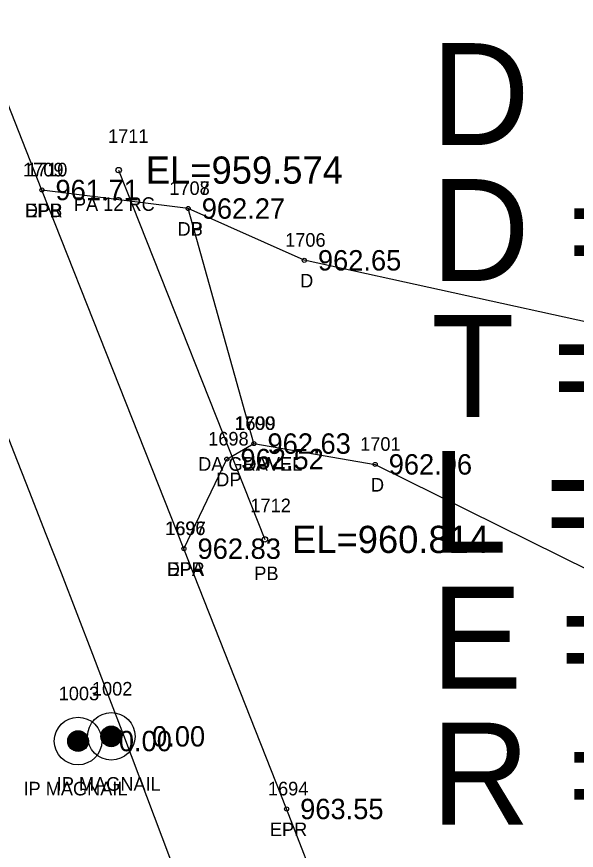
# Model space of a CAD drawing. Extents: x 1528109 to 1531398, y 1157799 to 1162548.
# Drawn here: x 1530615.5 to 1530656.7, y 1158820.1 to 1158881.4 of the extents above; entities that cross this region are included whole.
import ezdxf

# ---------------------------------------------------------------- set-up
doc = ezdxf.new("R2010")
doc.units = 0
for name, color, linetype in [('RD_EX_DR_Pipe', 7, 'Continuous'), ('RD_EX_DR_Pipe_txCode', 7, 'Continuous'), ('RD_EX_Driveway', 7, 'Continuous'), ('RD_EX_Driveway_txCode', 7, 'Continuous'), ('RD_EX_DV_Prop_txCode', 7, 'Continuous'), ('RD_EX_DV_PropPin', 7, 'Continuous'), ('RD_EX_Road', 7, 'Continuous'), ('RD_EX_Road_txCode', 7, 'Continuous'), ('RD_EX_TX_Driveway_ELEV', 7, 'Continuous'), ('RD_EX_TX_DV_Prop_ELEV', 7, 'Continuous'), ('RD_EX_TX_Road_ELEV', 7, 'Continuous'), ('RD_HC_Cl', 7, 'Continuous'), ('RD_HC_Data', 7, 'Continuous'), ('RD_SMD_Locator', 7, 'Continuous'), ('RD_TX_Pipe_ElevEX', 7, 'Continuous')]:
    doc.layers.add(name, color=color, linetype=linetype)

msp = doc.modelspace()

# ---------------------------------------------------------------- linework, layer by layer
at = {"layer": 'RD_EX_DR_Pipe'}
msp.add_line((1530622.995, 1158870.158), (1530633.756, 1158842.986), dxfattribs=at)
at = {"layer": 'RD_EX_Driveway'}
for points in [[(1530627.8, 1158842.302), (1530630.956, 1158848.893), (1530632.946, 1158850.037), (1530628.109, 1158867.33), (1530617.346, 1158868.693)], [(1530632.946, 1158850.037), (1530641.869, 1158848.504), (1530662.26, 1158838.421), (1530704.169, 1158845.738), (1530700.829, 1158858.174), (1530669.534, 1158856.332), (1530636.658, 1158863.52), (1530628.109, 1158867.33)]]:
    msp.add_lwpolyline(points, dxfattribs=at)
at = {"layer": 'RD_EX_DV_PropPin'}
for p, q in [((1530619.727, 1158827.441), (1530619.727, 1158828.856)), ((1530619.762, 1158827.428), (1530619.762, 1158828.869)), ((1530619.797, 1158827.417), (1530619.797, 1158828.88)), ((1530619.833, 1158827.408), (1530619.833, 1158828.89)), ((1530619.868, 1158827.401), (1530619.868, 1158828.897)), ((1530619.903, 1158827.395), (1530619.903, 1158828.903)), ((1530619.938, 1158827.391), (1530619.938, 1158828.907)), ((1530619.973, 1158827.389), (1530619.973, 1158828.909)), ((1530620.008, 1158827.388), (1530620.008, 1158828.91)), ((1530620.043, 1158827.389), (1530620.043, 1158828.909)), ((1530620.078, 1158827.391), (1530620.078, 1158828.907)), ((1530620.113, 1158827.395), (1530620.113, 1158828.903)), ((1530620.148, 1158827.401), (1530620.148, 1158828.897)), ((1530620.183, 1158827.408), (1530620.183, 1158828.89)), ((1530620.218, 1158827.417), (1530620.218, 1158828.88)), ((1530620.253, 1158827.428), (1530620.253, 1158828.869)), ((1530620.288, 1158827.441), (1530620.288, 1158828.856)), ((1530621.789, 1158828.126), (1530621.789, 1158828.865)), ((1530621.824, 1158828.069), (1530621.824, 1158828.922)), ((1530621.859, 1158828.021), (1530621.859, 1158828.969)), ((1530621.894, 1158827.98), (1530621.894, 1158829.01)), ((1530621.929, 1158827.944), (1530621.929, 1158829.046)), ((1530621.964, 1158827.913), (1530621.964, 1158829.077)), ((1530621.999, 1158827.885), (1530621.999, 1158829.105)), ((1530622.034, 1158827.861), (1530622.034, 1158829.13)), ((1530622.069, 1158827.839), (1530622.069, 1158829.151)), ((1530622.104, 1158827.819), (1530622.104, 1158829.171)), ((1530622.139, 1158827.802), (1530622.139, 1158829.188)), ((1530622.174, 1158827.788), (1530622.174, 1158829.203)), ((1530622.209, 1158827.775), (1530622.209, 1158829.216)), ((1530622.244, 1158827.764), (1530622.244, 1158829.227)), ((1530622.279, 1158827.754), (1530622.279, 1158829.236)), ((1530622.314, 1158827.747), (1530622.314, 1158829.243)), ((1530622.349, 1158827.741), (1530622.349, 1158829.249)), ((1530622.384, 1158827.737), (1530622.384, 1158829.253)), ((1530622.419, 1158827.735), (1530622.419, 1158829.255)), ((1530622.454, 1158827.734), (1530622.454, 1158829.256)), ((1530622.489, 1158827.735), (1530622.489, 1158829.255)), ((1530622.525, 1158827.737), (1530622.525, 1158829.253)), ((1530622.56, 1158827.741), (1530622.56, 1158829.249)), ((1530622.595, 1158827.747), (1530622.595, 1158829.243)), ((1530622.63, 1158827.754), (1530622.63, 1158829.236)), ((1530622.665, 1158827.764), (1530622.665, 1158829.227)), ((1530622.7, 1158827.775), (1530622.7, 1158829.216)), ((1530622.735, 1158827.788), (1530622.735, 1158829.203)), ((1530622.77, 1158827.802), (1530622.77, 1158829.188)), ((1530622.805, 1158827.819), (1530622.805, 1158829.171)), ((1530622.84, 1158827.839), (1530622.84, 1158829.151)), ((1530622.875, 1158827.861), (1530622.875, 1158829.13)), ((1530622.91, 1158827.885), (1530622.91, 1158829.105)), ((1530622.945, 1158827.913), (1530622.945, 1158829.077)), ((1530622.98, 1158827.944), (1530622.98, 1158829.046)), ((1530623.015, 1158827.98), (1530623.015, 1158829.01)), ((1530623.05, 1158828.021), (1530623.05, 1158828.969)), ((1530623.085, 1158828.069), (1530623.085, 1158828.922)), ((1530623.12, 1158828.126), (1530623.12, 1158828.865)), ((1530619.272, 1158827.953), (1530619.272, 1158828.345)), ((1530619.307, 1158827.851), (1530619.307, 1158828.447)), ((1530619.342, 1158827.779), (1530619.342, 1158828.518)), ((1530619.377, 1158827.722), (1530619.377, 1158828.575)), ((1530619.412, 1158827.675), (1530619.412, 1158828.623)), ((1530619.447, 1158827.634), (1530619.447, 1158828.664)), ((1530619.482, 1158827.598), (1530619.482, 1158828.7)), ((1530619.517, 1158827.567), (1530619.517, 1158828.731)), ((1530619.552, 1158827.539), (1530619.552, 1158828.759)), ((1530619.587, 1158827.514), (1530619.587, 1158828.783)), ((1530619.622, 1158827.493), (1530619.622, 1158828.805)), ((1530619.657, 1158827.473), (1530619.657, 1158828.825)), ((1530619.692, 1158827.456), (1530619.692, 1158828.842)), ((1530620.323, 1158827.456), (1530620.323, 1158828.842)), ((1530620.358, 1158827.473), (1530620.358, 1158828.825)), ((1530620.393, 1158827.493), (1530620.393, 1158828.805)), ((1530620.428, 1158827.514), (1530620.428, 1158828.783)), ((1530620.463, 1158827.539), (1530620.463, 1158828.759)), ((1530620.498, 1158827.567), (1530620.498, 1158828.731)), ((1530620.533, 1158827.598), (1530620.533, 1158828.7)), ((1530620.568, 1158827.634), (1530620.568, 1158828.664)), ((1530620.603, 1158827.675), (1530620.603, 1158828.623)), ((1530620.638, 1158827.722), (1530620.638, 1158828.575)), ((1530620.673, 1158827.779), (1530620.673, 1158828.518)), ((1530620.708, 1158827.851), (1530620.708, 1158828.447)), ((1530620.743, 1158827.953), (1530620.743, 1158828.345)), ((1530621.719, 1158828.299), (1530621.719, 1158828.691)), ((1530621.754, 1158828.197), (1530621.754, 1158828.793)), ((1530623.155, 1158828.197), (1530623.155, 1158828.793)), ((1530623.19, 1158828.299), (1530623.19, 1158828.691))]:
    msp.add_line(p, q, dxfattribs=at)
for centre, radius in [((1530622.454, 1158828.495), 1.75), ((1530620.008, 1158828.149), 1.75), ((1530620.008, 1158828.149), 0.761), ((1530622.454, 1158828.495), 0.761)]:
    msp.add_circle(centre, radius, dxfattribs=at)
at = {"layer": 'RD_EX_Road'}
msp.add_lwpolyline([(1530704.872, 1158597.47), (1530691.014, 1158649.877), (1530681.221, 1158687.321), (1530670.59, 1158724.996), (1530654.416, 1158774.072), (1530635.351, 1158823.151), (1530627.8, 1158842.302), (1530617.346, 1158868.693), (1530597.914, 1158918.043), (1530578.532, 1158967.566), (1530556.701, 1159015.656), (1530524.512, 1159062.454), (1530499.94, 1159086.31), (1530481.928, 1159100.117), (1530434.533, 1159126.999), (1530416.954, 1159134.125), (1530380.005, 1159145.606), (1530337.524, 1159156.438)], dxfattribs=at)
at = {"layer": 'RD_HC_Cl'}
msp.add_arc((1528951.998, 1158192.727), 1788.23, 15.397279, 21.95502, dxfattribs=at)
at = {"layer": 'RD_SMD_Locator'}
for centre, radius in [((1530622.995, 1158870.158), 0.2), ((1530617.346, 1158868.693), 0.15), ((1530617.346, 1158868.693), 0.15), ((1530628.109, 1158867.33), 0.15), ((1530628.109, 1158867.33), 0.15), ((1530636.658, 1158863.52), 0.15), ((1530632.946, 1158850.037), 0.15), ((1530632.946, 1158850.037), 0.15), ((1530630.956, 1158848.893), 0.15), ((1530641.869, 1158848.504), 0.15), ((1530633.756, 1158842.986), 0.2), ((1530627.8, 1158842.302), 0.15), ((1530627.8, 1158842.302), 0.15), ((1530620.008, 1158828.149), 0.15), ((1530622.455, 1158828.495), 0.15), ((1530635.351, 1158823.151), 0.15)]:
    msp.add_circle(centre, radius, dxfattribs=at)

# ---------------------------------------------------------------- texts
at = {"layer": 'RD_EX_DR_Pipe_txCode'}
for s, p in [('1711', (1530622.215, 1158872.158)), ('PA 12 RC', (1530619.703, 1158867.158)), ('1712', (1530632.693, 1158844.986)), ('PB', (1530632.977, 1158839.986))]:
    msp.add_text(s, height=1, dxfattribs=at).set_placement(p)
at = {"layer": 'RD_EX_Driveway_txCode'}
for s, p in [('1709', (1530615.96, 1158869.693)), ('1707', (1530626.723, 1158868.33)), ('1708', (1530626.723, 1158868.33)), ('DPB', (1530616.094, 1158866.693)), ('DB', (1530627.329, 1158865.33)), ('DP', (1530627.329, 1158865.33)), ('1706', (1530635.249, 1158864.52)), ('D', (1530636.351, 1158861.52)), ('1700', (1530631.521, 1158851.037)), ('1699', (1530631.576, 1158851.037)), ('1698', (1530629.586, 1158849.893)), ('1701', (1530640.767, 1158849.504)), ('DA GRAVEL', (1530628.844, 1158848.037)), ('DP', (1530632.167, 1158848.037)), ('DP', (1530630.177, 1158846.893)), ('D', (1530641.562, 1158846.504)), ('1697', (1530626.43, 1158843.302)), ('DPA', (1530626.532, 1158840.302))]:
    msp.add_text(s, height=1, dxfattribs=at).set_placement(p)
at = {"layer": 'RD_EX_DV_Prop_txCode'}
for s, p in [('1003', (1530618.582, 1158831.149)), ('1002', (1530621.029, 1158831.495)), ('IP MAGNAIL', (1530618.439, 1158824.495)), ('IP MAGNAIL', (1530615.992, 1158824.149))]:
    msp.add_text(s, height=1, dxfattribs=at).set_placement(p)
at = {"layer": 'RD_EX_Road_txCode'}
for s, p in [('1710', (1530616.243, 1158869.693)), ('EPR', (1530616.117, 1158866.693)), ('1696', (1530626.406, 1158843.302)), ('EPR', (1530626.572, 1158840.302)), ('1694', (1530633.981, 1158824.151)), ('EPR', (1530634.122, 1158821.151))]:
    msp.add_text(s, height=1, dxfattribs=at).set_placement(p)
at = {"layer": 'RD_EX_TX_Driveway_ELEV'}
for s, p in [('961.71', (1530618.346, 1158867.943)), ('962.27', (1530629.109, 1158866.58)), ('962.27', (1530629.109, 1158866.58)), ('962.65', (1530637.658, 1158862.77)), ('962.63', (1530633.946, 1158849.287)), ('962.63', (1530633.946, 1158849.287)), ('962.52', (1530631.956, 1158848.143)), ('962.96', (1530642.869, 1158847.754)), ('962.83', (1530628.8, 1158841.552))]:
    msp.add_text(s, height=1.5, dxfattribs=at).set_placement(p)
at = {"layer": 'RD_EX_TX_DV_Prop_ELEV'}
for p in [(1530623.008, 1158827.399), (1530625.455, 1158827.745)]:
    msp.add_text('0.00', height=1.5, dxfattribs=at).set_placement(p)
at = {"layer": 'RD_EX_TX_Road_ELEV'}
for s, p in [('961.71', (1530618.346, 1158867.943)), ('962.83', (1530628.8, 1158841.552)), ('963.55', (1530636.351, 1158822.401))]:
    msp.add_text(s, height=1.5, dxfattribs=at).set_placement(p)
at = {"layer": 'RD_HC_Data'}
for s, p in [('D', (1530646, 1158872)), ('D = 3%%d 12\' 15"', (1530646, 1158862)), ("T = 102.45'", (1530646, 1158852)), ("L = 204.67'", (1530646, 1158842)), ("E = 2.93'", (1530646, 1158832)), ("R = 1,788.23'", (1530646, 1158822))]:
    msp.add_text(s, height=7.5, dxfattribs=at).set_placement(p)
at = {"layer": 'RD_TX_Pipe_ElevEX'}
for s, p in [('EL=959.574', (1530624.995, 1158869.158)), ('EL=960.814', (1530635.756, 1158841.986))]:
    msp.add_text(s, height=2, dxfattribs=at).set_placement(p)

doc.saveas('drawing.dxf')
